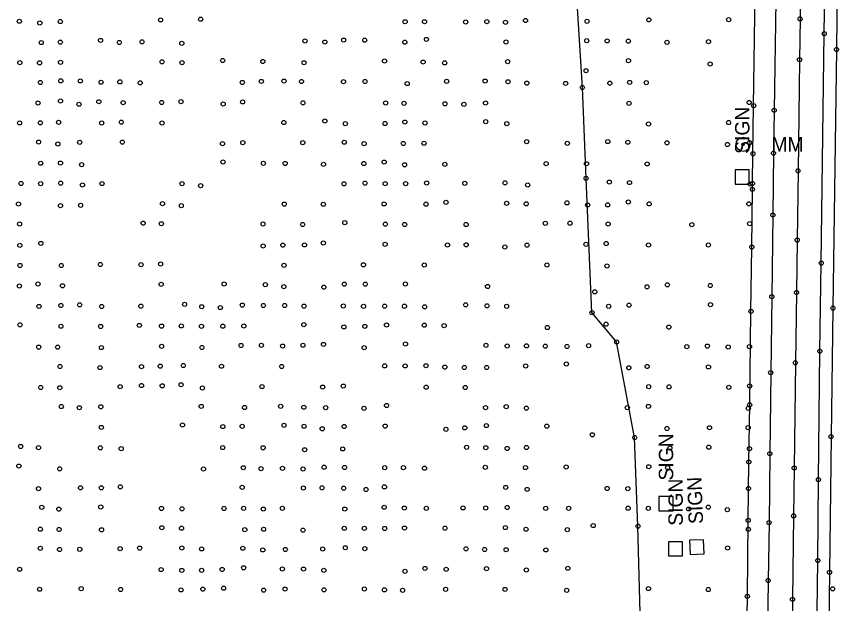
# Model space of a CAD drawing. Extents: x 20503438 to 20508873, y 7964251 to 7984667.
# Drawn here: x 20506282.7 to 20506681.6, y 7972754.9 to 7973039.7 of the extents above; entities that cross this region are included whole.
import ezdxf

# ---------------------------------------------------------------- set-up
doc = ezdxf.new("R2010")
doc.units = 0
for name, color, linetype in [('SurBreakLine', 7, 'Continuous'), ('SurDrainageArrowDown', 7, 'Continuous'), ('SurEdgeRoadPaved', 7, 'Continuous'), ('SurEdgeShoulderPaved', 7, 'Continuous'), ('SurPointsNonDTM', 7, 'Continuous'), ('SurRoadPoints', 7, 'Continuous'), ('SurSurveyPoints', 7, 'Continuous')]:
    doc.layers.add(name, color=color, linetype=linetype)

msp = doc.modelspace()

# ---------------------------------------------------------------- linework, layer by layer
at = {"layer": 'SurBreakLine'}
msp.add_lwpolyline([(20506663.33, 7973069.8), (20506662.94, 7973038.47), (20506662.68, 7973018.66), (20506661.96, 7972964.76), (20506661.55, 7972931.17), (20506661.22, 7972905.77), (20506660.66, 7972871.66), (20506660.1, 7972820.68), (20506659.81, 7972797.41), (20506659.27, 7972756.99), (20506658.77, 7972716.86), (20506658.27, 7972676.66), (20506657.84, 7972644.83), (20506657.39, 7972612.6), (20506656.92, 7972575.74), (20506656.4, 7972539.64), (20506655.94, 7972506.22), (20506655.78, 7972492.18), (20506655.64, 7972480.95), (20506655.39, 7972460.82)], dxfattribs=at)
at = {"layer": 'SurDrainageArrowDown'}
msp.add_lwpolyline([(20506582.39, 7972475.07), (20506582.65, 7972516.36), (20506588.45, 7972561.12), (20506586.2, 7972602.19), (20506585.43, 7972649.8), (20506585.69, 7972698.55), (20506585.31, 7972750.39), (20506584.27, 7972792.42), (20506582.67, 7972835.44), (20506573.89, 7972881.78), (20506561.94, 7972896), (20506559.1, 7972961.09), (20506557.3, 7973005.18), (20506553.75, 7973061.78), (20506550.66, 7973104.43), (20506542.34, 7973125.73), (20506530.42, 7973148.91), (20506526.31, 7973153.75), (20506522.97, 7973156.02), (20506521.88, 7973157.28)], dxfattribs=at)
at = {"layer": 'SurEdgeRoadPaved'}
for points in [[(20506653.73, 7971380.9), (20506654.7, 7971481.23), (20506657.38, 7971669.1), (20506659.55, 7971851.97), (20506660.98, 7971956.86), (20506661.2, 7971992.92), (20506662.91, 7972124.86), (20506664.2, 7972212.79), (20506664.61, 7972246.33), (20506665.88, 7972358.05), (20506666.2, 7972384.01), (20506666.76, 7972424.32), (20506667.23, 7972453.6), (20506667.84, 7972505.25), (20506669.4, 7972614.97), (20506671.57, 7972775.78), (20506671.83, 7972814.97), (20506672.54, 7972877.32), (20506673.22, 7972920.01), (20506674.66, 7973031.32), (20506676.22, 7973136.41)], [(20506632.33, 7972453.69), (20506633.86, 7972497.27), (20506634.28, 7972509.08), (20506634.46, 7972539.89), (20506634.5, 7972542.72), (20506634.87, 7972568.1), (20506635.54, 7972614.89), (20506635.94, 7972648.03), (20506636.41, 7972690.83), (20506636.74, 7972718.9), (20506637.35, 7972758.4), (20506637.77, 7972795.25), (20506638.07, 7972823.54), (20506638.49, 7972851.26), (20506639.1, 7972896.6), (20506639.51, 7972927.78), (20506639.8, 7972955.82), (20506639.83, 7972958.63), (20506640.06, 7972973.05), (20506640.4, 7972996.37), (20506641.08, 7973051.14)], [(20506651.1, 7973047.21), (20506650.35, 7972994.14), (20506650.04, 7972973.33), (20506649.71, 7972943.4), (20506649.2, 7972903.71), (20506648.69, 7972866.86), (20506648.26, 7972827.56), (20506647.9, 7972794.1), (20506647.45, 7972766.08), (20506646.99, 7972729.71), (20506646.31, 7972681.9), (20506646.08, 7972653.99), (20506645.65, 7972612.99), (20506644.96, 7972574.78), (20506644.4, 7972542.36), (20506643.74, 7972497.26), (20506643.62, 7972491.27), (20506643.19, 7972470.31), (20506643.14, 7972436.02)]]:
    msp.add_lwpolyline(points, dxfattribs=at)
at = {"layer": 'SurEdgeShoulderPaved'}
msp.add_lwpolyline([(20506681.39, 7973102.17), (20506680.61, 7973023.61), (20506678.88, 7972898.17), (20506677.96, 7972835.87), (20506677.24, 7972770.07), (20506676.37, 7972707.06), (20506676.17, 7972692.84), (20506676.07, 7972684.34), (20506675.16, 7972614.83), (20506674.88, 7972581.01), (20506673.14, 7972470.38), (20506671.33, 7972306.45)], dxfattribs=at)
at = {"layer": 'SurPointsNonDTM'}
for centre in [(20506559.1, 7973013.31), (20506563.32, 7972906.1), (20506562.11, 7972836.76), (20506562.56, 7972792.71)]:
    msp.add_circle(centre, 1, dxfattribs=at)
at = {"layer": 'SurRoadPoints'}
for points in [[(20506638.3, 7972961.79), (20506638.3, 7972961.79), (20506638.3, 7972965.22), (20506631.45, 7972965.22), (20506631.45, 7972958.37), (20506638.3, 7972958.37), (20506638.3, 7972961.79)], [(20506601.31, 7972803.36), (20506601.31, 7972803.36), (20506601.31, 7972806.79), (20506594.45, 7972806.79), (20506594.45, 7972799.93), (20506601.31, 7972799.93), (20506601.31, 7972803.36)], [(20506616.27, 7972782.42), (20506616.27, 7972782.42), (20506616.14, 7972785.84), (20506609.3, 7972785.58), (20506609.56, 7972778.74), (20506616.4, 7972779), (20506616.27, 7972782.42)], [(20506605.96, 7972781.42), (20506605.96, 7972781.42), (20506605.96, 7972784.85), (20506599.1, 7972784.85), (20506599.1, 7972777.99), (20506605.96, 7972777.99), (20506605.96, 7972781.42)]]:
    msp.add_lwpolyline(points, dxfattribs=at)
for radius in [3.43, 0.571]:
    msp.add_circle((20506635.31, 7972977.63), radius, dxfattribs=at)
at = {"layer": 'SurSurveyPoints'}
for centre in [(20506284.1, 7973037.33), (20506294.01, 7973036.47), (20506303.96, 7973037.18), (20506352.63, 7973037.97), (20506372.08, 7973038.31), (20506471.28, 7973037.08), (20506480.71, 7973037.08), (20506500.67, 7973036.96), (20506510.93, 7973037.13), (20506520, 7973036.8), (20506529.71, 7973037.67), (20506559.58, 7973037.28), (20506589.56, 7973038.02), (20506628.28, 7973038.12), (20506662.94, 7973038.47), (20506323.5, 7973028.03), (20506441.47, 7973028.2), (20506451.69, 7973028.13), (20506481.61, 7973028.51), (20506559.41, 7973027.88), (20506569.32, 7973027.79), (20506674.66, 7973031.32), (20506294.72, 7973026.98), (20506303.96, 7973027.18), (20506332.63, 7973027.03), (20506343.61, 7973027.35), (20506362.91, 7973026.6), (20506422.72, 7973027.76), (20506432.32, 7973027.23), (20506471.16, 7973027.16), (20506520.19, 7973027.24), (20506579.58, 7973027.65), (20506598.34, 7973027.1), (20506618.49, 7973027.41), (20506680.61, 7973023.61), (20506284.34, 7973017.22), (20506293.9, 7973017.14), (20506304.08, 7973017.4), (20506353.34, 7973017.63), (20506362.99, 7973017.26), (20506382.77, 7973018.27), (20506402.26, 7973017.82), (20506422.25, 7973017.19), (20506461.27, 7973018.05), (20506480.05, 7973017.52), (20506490.46, 7973017.13), (20506521.07, 7973017.73), (20506579.65, 7973018.18), (20506619.31, 7973016.59), (20506662.68, 7973018.66), (20506304.2, 7973008.41), (20506313.73, 7973008.39), (20506332.88, 7973007.91), (20506401.53, 7973008.15), (20506412.5, 7973008.3), (20506421.01, 7973008.1), (20506441.39, 7973008.02), (20506451.84, 7973008.12), (20506491.43, 7973008.18), (20506510.1, 7973008.3), (20506521.2, 7973007.98), (20506294.29, 7973007.62), (20506323.76, 7973007.73), (20506342.7, 7973007.46), (20506392.31, 7973007.64), (20506472.31, 7973007.1), (20506530.36, 7973007.32), (20506549.17, 7973007.18), (20506557.3, 7973005.18), (20506570.62, 7973007.28), (20506580.22, 7973007.66), (20506588.3, 7973007.53), (20506293.18, 7972997.7), (20506304.04, 7972998.67), (20506313.03, 7972997.07), (20506322.66, 7972998.29), (20506334.46, 7972997.82), (20506353.13, 7972997.92), (20506362.51, 7972998.34), (20506383, 7972997.17), (20506392.41, 7972998.19), (20506421.69, 7972997.77), (20506461.84, 7972997.7), (20506470.79, 7972997.51), (20506490.6, 7972997.3), (20506499.8, 7972997.03), (20506510.28, 7972997.68), (20506579.9, 7972997.54), (20506638.25, 7972997.91), (20506640.4, 7972996.37), (20506650.35, 7972994.14), (20506284.2, 7972988.01), (20506294.27, 7972988.07), (20506303.16, 7972988.32), (20506324.04, 7972987.97), (20506333.54, 7972988.38), (20506353.34, 7972987.97), (20506412.43, 7972988.19), (20506432.34, 7972988.93), (20506471.14, 7972988.42), (20506480.91, 7972987.98), (20506510.4, 7972988.62), (20506628.24, 7972988.19), (20506442.28, 7972987.65), (20506461.56, 7972987.71), (20506520.61, 7972987.68), (20506589.4, 7972987.46), (20506293.43, 7972978.72), (20506302.79, 7972977.77), (20506313.37, 7972978.61), (20506334.09, 7972978.67), (20506382.65, 7972977.94), (20506392.51, 7972978.43), (20506421.62, 7972978.42), (20506441.75, 7972978.64), (20506451.39, 7972977.93), (20506470.42, 7972978.02), (20506480.44, 7972978.16), (20506530.25, 7972978.95), (20506549.97, 7972978.1), (20506569.62, 7972978.96), (20506579.36, 7972978.63), (20506598.37, 7972978.37), (20506627.69, 7972977.54), (20506638.46, 7972978.47), (20506640.06, 7972973.05), (20506650.04, 7972973.33), (20506294.45, 7972968.45), (20506304.03, 7972968.53), (20506382.9, 7972969.07), (20506402.52, 7972968.4), (20506413.07, 7972968.36), (20506451.24, 7972968.3), (20506461.12, 7972969.02), (20506539.71, 7972968.25), (20506559.31, 7972968.22), (20506588.73, 7972968.12), (20506314.29, 7972967.79), (20506431.68, 7972967.9), (20506471.03, 7972967.71), (20506490.57, 7972967.91), (20506661.96, 7972964.76), (20506559.1, 7972961.09), (20506284.92, 7972958.61), (20506294.44, 7972958.56), (20506304.1, 7972958.78), (20506314.74, 7972957.93), (20506324.2, 7972958.58), (20506363.03, 7972958.52), (20506372.07, 7972957.59), (20506441.6, 7972958.47), (20506451.86, 7972958.8), (20506461.59, 7972958.57), (20506471.55, 7972958.57), (20506481.73, 7972958.86), (20506500.23, 7972958.73), (20506519.73, 7972958.95), (20506530.76, 7972957.93), (20506570.4, 7972959.32), (20506580.15, 7972959.07), (20506638.7, 7972958.36), (20506639.83, 7972958.63), (20506639.8, 7972955.82), (20506283.68, 7972948.66), (20506313.81, 7972948.05), (20506353.56, 7972948.85), (20506412.63, 7972948.63), (20506431.58, 7972948.56), (20506461.09, 7972948.73), (20506481.42, 7972948.58), (20506491.1, 7972949.48), (20506520.56, 7972949), (20506530.05, 7972948.76), (20506549.8, 7972949.23), (20506559.83, 7972948.18), (20506569.59, 7972948.26), (20506579.61, 7972949.65), (20506589.7, 7972948.74), (20506638.08, 7972948.76), (20506304.04, 7972947.88), (20506362.66, 7972947.9), (20506649.71, 7972943.4), (20506284.2, 7972939), (20506344.18, 7972939.41), (20506353.01, 7972939.11), (20506402.36, 7972938.96), (20506421.55, 7972938.73), (20506442, 7972939.61), (20506461.72, 7972938.91), (20506471.07, 7972938.76), (20506500.88, 7972938.72), (20506539.31, 7972939.29), (20506551.27, 7972939.37), (20506569.8, 7972939), (20506610.4, 7972938.67), (20506638.48, 7972939.12), (20506284.32, 7972928.62), (20506294.54, 7972929.57), (20506402.41, 7972928.34), (20506411.93, 7972928.71), (20506422.45, 7972928.84), (20506431.59, 7972929.77), (20506461.58, 7972929.13), (20506491.84, 7972928.8), (20506500.89, 7972928.9), (20506530.41, 7972928.71), (20506559.06, 7972929.1), (20506568.85, 7972929.5), (20506589.37, 7972928.78), (20506618.46, 7972928.78), (20506661.55, 7972931.17), (20506519.69, 7972927.86), (20506639.51, 7972927.78), (20506284.4, 7972918.89), (20506304.43, 7972918.86), (20506323.42, 7972919.33), (20506343.13, 7972919.26), (20506352.65, 7972919.57), (20506412.5, 7972918.95), (20506451.06, 7972919.2), (20506480.57, 7972919.1), (20506540.09, 7972919.12), (20506569.26, 7972918.64), (20506673.22, 7972920.01), (20506284.13, 7972908.92), (20506293.16, 7972909.89), (20506305.04, 7972909.02), (20506352.92, 7972909.71), (20506383.45, 7972909.88), (20506403.44, 7972909.57), (20506412.44, 7972908.62), (20506431.85, 7972908.36), (20506441.75, 7972909.8), (20506451.93, 7972909.79), (20506471.43, 7972909.87), (20506511.29, 7972908.69), (20506588.7, 7972908.53), (20506598.51, 7972909.49), (20506619.34, 7972909.15), (20506661.22, 7972905.77), (20506649.2, 7972903.71), (20506293.64, 7972899.01), (20506304.25, 7972899.46), (20506313.36, 7972899.79), (20506324.04, 7972898.97), (20506343.07, 7972899.14), (20506364.27, 7972900.04), (20506372.6, 7972898.85), (20506381.59, 7972898.44), (20506392.27, 7972899.65), (20506402.53, 7972899.47), (20506412.85, 7972899.46), (20506422.23, 7972899.15), (20506441.31, 7972899.2), (20506451.11, 7972899.07), (20506461.35, 7972899.14), (20506470.96, 7972899.11), (20506480.75, 7972898.81), (20506500.66, 7972899.79), (20506511.05, 7972899.29), (20506520.59, 7972899.05), (20506570.07, 7972899.07), (20506579.91, 7972899.6), (20506619.45, 7972899.86), (20506639.1, 7972896.6), (20506678.88, 7972898.17), (20506561.94, 7972896), (20506284.4, 7972890.09), (20506304.27, 7972889.39), (20506323.55, 7972889.3), (20506342.34, 7972889.79), (20506353.1, 7972889.46), (20506362.67, 7972889.55), (20506372.46, 7972889.35), (20506382.82, 7972889.41), (20506393.02, 7972889.5), (20506422.15, 7972890.15), (20506441.57, 7972889.06), (20506451.75, 7972889.31), (20506462.28, 7972890.02), (20506480.56, 7972889.9), (20506490.21, 7972889.66), (20506540.33, 7972888.76), (20506568.81, 7972890.38), (20506599.25, 7972888.97), (20506421.69, 7972880.18), (20506431.66, 7972880.58), (20506471.45, 7972880.81), (20506573.89, 7972881.78), (20506293.5, 7972879.28), (20506302.65, 7972879.24), (20506323.91, 7972879.04), (20506353.11, 7972879.63), (20506372.68, 7972879.1), (20506391.68, 7972880.08), (20506401.56, 7972880.11), (20506411.83, 7972879.78), (20506451.4, 7972878.98), (20506510.5, 7972880.14), (20506520.82, 7972879.79), (20506530.18, 7972879.87), (20506539.29, 7972879.74), (20506549.88, 7972879.57), (20506560.32, 7972879.99), (20506607.97, 7972879.52), (20506617.97, 7972879.76), (20506628.07, 7972879.34), (20506638.37, 7972879.52), (20506672.54, 7972877.32), (20506303.84, 7972869.87), (20506323.25, 7972869.34), (20506343.36, 7972869.81), (20506352.45, 7972870.04), (20506363.68, 7972870.35), (20506382.17, 7972870), (20506411.4, 7972869.88), (20506461.36, 7972870.17), (20506471.3, 7972870.16), (20506481.4, 7972870.24), (20506490.57, 7972869.57), (20506500, 7972869.4), (20506510.83, 7972869.38), (20506529.79, 7972870.12), (20506549.52, 7972871.11), (20506579.83, 7972869.24), (20506588.72, 7972869.86), (20506618.47, 7972869.67), (20506660.66, 7972871.66), (20506648.69, 7972866.86), (20506343.36, 7972860.63), (20506353.42, 7972860.51), (20506362.57, 7972861.03), (20506441.29, 7972860.38), (20506638.48, 7972860.46), (20506294.42, 7972859.7), (20506303.73, 7972859.57), (20506333.01, 7972860.07), (20506372.92, 7972859.42), (20506401.86, 7972860.13), (20506431.27, 7972859.88), (20506481.51, 7972859.82), (20506500.45, 7972859.68), (20506589.51, 7972860.06), (20506599.37, 7972859.98), (20506628.38, 7972859.74), (20506304.49, 7972850.44), (20506313.21, 7972849.86), (20506323.63, 7972850.33), (20506372.34, 7972850.52), (20506393.37, 7972849.97), (20506410.91, 7972850.58), (20506422.15, 7972850.11), (20506432.76, 7972849.9), (20506451.32, 7972849.59), (20506462.28, 7972850.97), (20506510.31, 7972849.9), (20506520.34, 7972850.4), (20506530.14, 7972849.65), (20506579.1, 7972849.93), (20506589.36, 7972850.51), (20506637.85, 7972849.61), (20506638.49, 7972851.26), (20506323.86, 7972840.33), (20506363.24, 7972841.48), (20506382.85, 7972840.73), (20506392.23, 7972840.88), (20506412.55, 7972841.31), (20506422.25, 7972840.89), (20506441.7, 7972840.77), (20506461.59, 7972840.96), (20506510.73, 7972841.21), (20506540.02, 7972840.94), (20506431.06, 7972839.66), (20506491.08, 7972839.38), (20506500.23, 7972840.11), (20506598.39, 7972839.82), (20506618.97, 7972840.17), (20506637.72, 7972840.23), (20506582.67, 7972835.44), (20506677.96, 7972835.87), (20506284.75, 7972831.1), (20506293.4, 7972830.49), (20506323.42, 7972830.42), (20506333.52, 7972830.01), (20506382.79, 7972830.55), (20506402.38, 7972830.45), (20506422.52, 7972829.5), (20506441.02, 7972829.89), (20506501.12, 7972830.69), (20506510.43, 7972830.46), (20506520.79, 7972830.12), (20506530.16, 7972830.59), (20506599.77, 7972830.34), (20506618.64, 7972830.73), (20506638.37, 7972830.03), (20506648.26, 7972827.56), (20506283.85, 7972821.58), (20506392.73, 7972820.77), (20506401.4, 7972820.33), (20506411.77, 7972820.48), (20506432.01, 7972821.02), (20506441.9, 7972820.89), (20506461.39, 7972820.8), (20506470.47, 7972820.83), (20506480.68, 7972820.53), (20506510.2, 7972820.99), (20506529.67, 7972820.85), (20506549.44, 7972821.12), (20506589.52, 7972821.25), (20506598.7, 7972820.85), (20506638.07, 7972823.54), (20506660.1, 7972820.68), (20506303.7, 7972820.24), (20506373.43, 7972820.16), (20506421.77, 7972820.14), (20506671.83, 7972814.97), (20506293.39, 7972810.63), (20506313.77, 7972811.03), (20506323.89, 7972811.04), (20506333.13, 7972811.49), (20506392.23, 7972811.27), (20506421.93, 7972810.93), (20506430.99, 7972811.02), (20506441.49, 7972810.86), (20506452.34, 7972810.23), (20506461.25, 7972811.48), (20506520.11, 7972811.23), (20506530.52, 7972810.25), (20506569.32, 7972810.73), (20506579.34, 7972810.6), (20506637.92, 7972810.71), (20506294.98, 7972801.56), (20506303.23, 7972800.69), (20506323.61, 7972801.72), (20506353.07, 7972801.02), (20506363.04, 7972800.83), (20506383.41, 7972800.98), (20506392.9, 7972801.06), (20506402.46, 7972800.71), (20506411.75, 7972801.05), (20506442.01, 7972800.72), (20506461.11, 7972801.6), (20506470.91, 7972801.2), (20506481.58, 7972801.09), (20506499.35, 7972801.28), (20506510.4, 7972801.23), (20506520.81, 7972801.48), (20506539.51, 7972801.07), (20506550.64, 7972801.09), (20506579.49, 7972801.13), (20506589.27, 7972801.1), (20506608.85, 7972800.79), (20506618.39, 7972801.64), (20506627.61, 7972800.42), (20506659.81, 7972797.41), (20506584.27, 7972792.42), (20506637.77, 7972795.25), (20506647.9, 7972794.1), (20506294.32, 7972790.95), (20506303.39, 7972790.82), (20506323.98, 7972790.68), (20506353.23, 7972791.66), (20506362.79, 7972791.43), (20506393.48, 7972790.76), (20506402.61, 7972790.94), (20506421.71, 7972790.5), (20506441.77, 7972791.41), (20506451.5, 7972791.38), (20506461.34, 7972791.32), (20506471, 7972791.5), (20506490.68, 7972791.45), (20506519.95, 7972791.74), (20506529.98, 7972790.94), (20506549.96, 7972790.74), (20506637.84, 7972790.94), (20506294.29, 7972781.68), (20506303.6, 7972781.11), (20506313.41, 7972781.2), (20506332.99, 7972781.5), (20506342.48, 7972781.79), (20506362.94, 7972781.86), (20506372.56, 7972781.4), (20506392.55, 7972781.72), (20506402.22, 7972780.9), (20506413.19, 7972781.13), (20506431.32, 7972781.37), (20506442.24, 7972781.96), (20506451.72, 7972781.54), (20506500.81, 7972781.45), (20506509.84, 7972781.11), (20506520.29, 7972781), (20506539.57, 7972780.91), (20506627.78, 7972781.84), (20506671.57, 7972775.78), (20506284.23, 7972771.54), (20506352.89, 7972771.37), (20506362.91, 7972770.96), (20506372.55, 7972771.01), (20506382.51, 7972771.44), (20506392.95, 7972772.25), (20506411.71, 7972771.65), (20506421.98, 7972771.62), (20506431.84, 7972771.02), (20506471.23, 7972770.54), (20506480.93, 7972771.94), (20506491.19, 7972771.51), (20506510.79, 7972771.81), (20506530.13, 7972771.17), (20506550.24, 7972772.01), (20506677.24, 7972770.07), (20506647.45, 7972766.08), (20506293.92, 7972761.84), (20506314.11, 7972762.12), (20506333.21, 7972761.73), (20506362.54, 7972761.51), (20506373.14, 7972761.86), (20506383.2, 7972762.33), (20506402.68, 7972761.38), (20506413.03, 7972761.91), (20506431.91, 7972761.56), (20506451.53, 7972761.97), (20506461.25, 7972761.53), (20506470.05, 7972761.32), (20506490.92, 7972761.8), (20506519.76, 7972761.75), (20506549.71, 7972761.31), (20506589.37, 7972762.16), (20506618.37, 7972761.69), (20506678.71, 7972762.02), (20506637.35, 7972758.4), (20506659.27, 7972756.99)]:
    msp.add_circle(centre, 1, dxfattribs=at)

# ---------------------------------------------------------------- texts
at = {"layer": 'SurRoadPoints'}
for s, rotation, p in [('SIGN', 90, (20506638.38, 7972973)), ('MM', 360, (20506649.02, 7972974.13)), ('SIGN', 90, (20506601.38, 7972814.57)), ('SIGN', 90, (20506606.03, 7972792.63)), ('SIGN', 92.1737, (20506615.92, 7972793.62))]:
    msp.add_text(s, height=6.995, rotation=rotation, dxfattribs=at).set_placement(p)

doc.saveas('drawing.dxf')
